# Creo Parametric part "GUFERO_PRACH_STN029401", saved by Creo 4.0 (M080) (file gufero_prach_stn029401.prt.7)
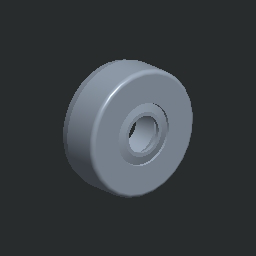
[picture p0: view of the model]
Units: millimeter Kilogram Sec (mmKs); MM, KILOGRAM, SECS
Materials in the file: POLYURETAN

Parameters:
  NAZOV = "GUFERO_PRACH_STN029401"
  NORMA = "STN 02 9401"
  NAZOV_1 = "START_PART_IPM"
  PTC_MATERIAL_NAME = "POLYURETAN"
  PRO_UNIT_SYS = "IPM (mmkgsecC)"

Other parameters: HMOTNOST, HUSTOTA, HMOTNOST_1, HUSTOTA_1, D9, D2, D7, D5, D6, D0, D4, D1, D3, D8, D10, D12, D13, D15, D16

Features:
  1. round
  2. chamfer

Named dimensions: male_d, velke_D

Layers: 1, 2, 3, 4, 5, 6, 7, 8, 9, 10, 11, 12, 13, 14, 15, 16, 17, 18, 19, 20, 21, 22, 23, 24, 25, 26, 27, 28, 29, 30, 31, 32

Family table entries: GENERIC, GUFERO_P_6_16_7, GUFERO_PRACH_STN029401, value(d_val), 2/0, value(i_val), GUFERO_P_6_22_7, GUFERO_PRACH_STN029401, 2/6, GUFERO_P_7_22_7, GUFERO_PRACH_STN029401, 2/6, GUFERO_P_8_16_7, GUFERO_PRACH_STN029401, !/ , 2/0, GUFERO_P_8_22_7, GUFERO_PRACH_STN029401, !/ , 2/6, GUFERO_P_8_24_7, GUFERO_PRACH_STN029401, !/ , 2/8, GUFERO_P_9_22_7, GUFERO_PRACH_STN029401, !/", 2/6, GUFERO_P_9_24_7, GUFERO_PRACH_STN029401, !/", 2/8, GUFERO_P_9_26_7, GUFERO_PRACH_STN029401, !/", 2/:, GUFERO_P_10_19_7, GUFERO_PRACH_STN029401, !/$, 2/6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

Surfaces: 14 cone, 8 cylinder, 6 plane, 2 torus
